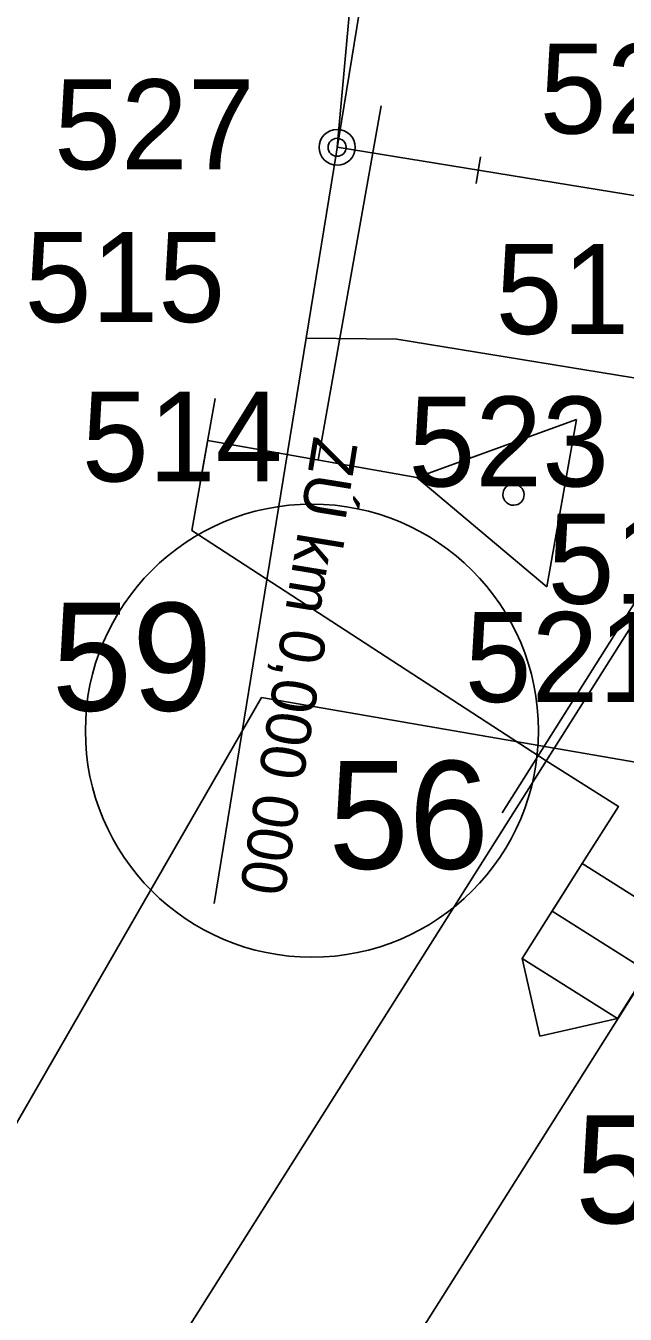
# Model space of a CAD drawing. Extents: x -743546 to -74, y -1128126 to -103.
# Drawn here: x -743185.96 to -743179.3, y -1127109.43 to -1127095.1 of the extents above; entities that cross this region are included whole.
import ezdxf

# ---------------------------------------------------------------- set-up
doc = ezdxf.new("R2010")
doc.units = 0
for name, color, linetype in [('_SVAH - Přesunutá', 7, 'Continuous'), ('_Zabezpečovací zařízení', 7, 'Continuous'), ('_Zabezpečovací zařízení_trasa', 7, 'Continuous'), ('bublina_fialová_čára_tenká', 7, 'Continuous'), ('KOMUNIKACE_KRAJNICE', 7, 'Continuous'), ('křížek', 7, 'Continuous'), ('křížky', 7, 'Continuous'), ('OSA_KOMUNIKACE', 7, 'Continuous'), ('OSA_POP', 7, 'Continuous'), ('SMER_VYS_VYROVNANI', 7, 'Continuous'), ('Vrstva 53', 7, 'Continuous'), ('Vrstva 60', 7, 'Continuous'), ('ŽBP', 7, 'Continuous')]:
    doc.layers.add(name, color=color, linetype=linetype)

# ---------------------------------------------------------------- blocks, each defined once
blk = doc.blocks.new('AeccTickCircle')
blk.add_circle((0, 0), 0.5)
blk = doc.blocks.new('POINT_DISPLAY')
blk.add_line((0, 0), (0, 0))

msp = doc.modelspace()

# ---------------------------------------------------------------- linework, layer by layer
at = {"layer": '_SVAH - Přesunutá'}
msp.add_lwpolyline([(-743178.679, -1127100.707), (-743180.665, -1127103.853)], dxfattribs=at)
at = {"layer": '_Zabezpečovací zařízení'}
for p, q in [((-743182.709, -1127099.929), (-743182.011, -1127095.99)), ((-743183.857, -1127099.245), (-743184.022, -1127100.176)), ((-743181.613, -1127100.122), (-743179.836, -1127099.477)), ((-743179.836, -1127099.477), (-743180.166, -1127101.338)), ((-743181.613, -1127100.122), (-743183.939, -1127099.711)), ((-743180.166, -1127101.338), (-743181.613, -1127100.122)), ((-743179.773, -1127104.416), (-743180.44, -1127105.473)), ((-743178.716, -1127105.083), (-743179.773, -1127104.416)), ((-743179.05, -1127105.611), (-743180.107, -1127104.945)), ((-743179.383, -1127106.14), (-743178.716, -1127105.083)), ((-743180.44, -1127105.473), (-743179.383, -1127106.14)), ((-743180.44, -1127105.473), (-743180.245, -1127106.335)), ((-743180.245, -1127106.335), (-743179.383, -1127106.14))]:
    msp.add_line(p, q, dxfattribs=at)
msp.add_lwpolyline([(-743179.773, -1127104.416), (-743180.107, -1127104.945), (-743179.05, -1127105.611), (-743178.716, -1127105.083), (-743179.773, -1127104.416)], dxfattribs=at)
for start, end in [(79.9608, 259.9608), (259.9608, 79.9608)]:
    msp.add_arc((-743180.538, -1127100.313), 0.118, start, end, dxfattribs=at)
at = {"layer": '_Zabezpečovací zařízení_trasa'}
for points in [[(-743049.28, -1126895.951), (-743072.487, -1126932.751), (-743098.647, -1126974.146), (-743125.94, -1127017.384), (-743152.604, -1127059.608), (-743175.023, -1127095.116), (-743199.163, -1127133.346), (-743215.971, -1127159.941), (-743232.818, -1127186.515), (-743247.456, -1127209.811), (-743254.52, -1127221.639), (-743261.299, -1127233.691), (-743264.155, -1127239.195), (-743264.862, -1127241.108), (-743267.337, -1127245.816)], [(-743183.942, -1127099.727), (-743184.117, -1127100.711), (-743180.174, -1127103.274)], [(-743180.542, -1127103.041), (-743180.542, -1127103.041)], [(-743179.773, -1127104.416), (-743179.372, -1127103.78), (-743180.174, -1127103.274)]]:
    msp.add_lwpolyline(points, dxfattribs=at)
at = {"layer": 'bublina_fialová_čára_tenká'}
msp.add_line((-743177.808, -1127044.792), (-743182.5, -1127096.45), dxfattribs=at)
at = {"layer": 'KOMUNIKACE_KRAJNICE'}
for q in [(-743182.159, -1127094.376), (-743181.834, -1127098.584)]:
    msp.add_line((-743182.845, -1127098.574), q, dxfattribs=at)
msp.add_lwpolyline([(-743178.176, -1127099.18), (-743181.834, -1127098.584)], dxfattribs=at)
at = {"layer": 'OSA_KOMUNIKACE'}
msp.add_line((-743164.284, -1127099.415), (-743182.5, -1127096.45), dxfattribs=at)
at = {"layer": 'OSA_POP'}
for p, q in [((-743180.954, -1127096.853), (-743180.906, -1127096.557)), ((-743182.845, -1127098.574), (-743183.869, -1127104.859))]:
    msp.add_line(p, q, dxfattribs=at)
at = {"layer": 'SMER_VYS_VYROVNANI'}
msp.add_lwpolyline([(-743178.712, -1127105.086), (-743197.526, -1127134.888)], dxfattribs=at)
at = {"layer": 'Vrstva 53'}
for points in [[(-743280.26, -1127263.68), (-743264.54, -1127233.06), (-743246.95, -1127204.21), (-743235.54, -1127186.77), (-743205.03, -1127140.21), (-743183.34, -1127102.57)], [(-743183.34, -1127102.57), (-743171.62, -1127104.6), (-743183.01, -1127122.02), (-743195.51, -1127141.13), (-743203.92, -1127154.43), (-743215.95, -1127172.74), (-743210.36, -1127174.02), (-743237.28, -1127205.49), (-743245.75, -1127220.06), (-743259.48, -1127245.93)]]:
    msp.add_lwpolyline(points, dxfattribs=at)
at = {"layer": 'Vrstva 60'}
for p, q in [((-743182.5, -1127096.45), (-743182.5, -1127096.45)), ((-743182.846, -1127098.574), (-743182.846, -1127098.574)), ((-743181.834, -1127098.584), (-743181.834, -1127098.584)), ((-743183.942, -1127099.727), (-743183.942, -1127099.727)), ((-743184.117, -1127100.711), (-743184.117, -1127100.711)), ((-743180.174, -1127103.274), (-743180.174, -1127103.274)), ((-743179.372, -1127103.78), (-743179.372, -1127103.78)), ((-743179.774, -1127104.416), (-743179.774, -1127104.416))]:
    msp.add_line(p, q, dxfattribs=at)
at = {"layer": 'ŽBP'}
msp.add_circle((-743182.78, -1127102.938), 2.52, dxfattribs=at)

# ---------------------------------------------------------------- block references
at = {"layer": 'křížek', "xscale": 10, "yscale": 10, "rotation": 61.14491455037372}
for p in [(-743182.5, -1127096.45), (-743182.846, -1127098.574), (-743181.834, -1127098.584)]:
    msp.add_blockref('POINT_DISPLAY', p, dxfattribs=at)
at = {"layer": 'křížky', "xscale": 10, "yscale": 10, "rotation": 61.14491455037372}
for p in [(-743183.942, -1127099.727), (-743184.117, -1127100.711), (-743180.174, -1127103.274), (-743179.372, -1127103.78), (-743179.774, -1127104.416)]:
    msp.add_blockref('POINT_DISPLAY', p, dxfattribs=at)
at = {"layer": 'OSA_POP', "rotation": -9.247996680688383}
for xscale, yscale in [(0.4, 0.39999999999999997), (0.2, 0.19999999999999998)]:
    msp.add_blockref('AeccTickCircle', (-743182.5, -1127096.45), dxfattribs=dict(at, xscale=xscale, yscale=yscale))

# ---------------------------------------------------------------- texts
at = {"layer": 'OSA_POP'}
msp.add_text('ZÚ km 0,000 000', height=0.5, rotation=260.752, dxfattribs=at).set_placement((-743182.76, -1127099.653))
at = {"layer": 'Vrstva 60'}
for s, height, p in [('526', 1, (-743180.247, -1127096.297)), ('527', 1, (-743185.648, -1127096.694)), ('515', 1, (-743185.977, -1127098.393)), ('513', 1, (-743180.737, -1127098.526)), ('514', 1, (-743185.34, -1127100.166)), ('523', 1, (-743181.707, -1127100.222)), ('512', 1, (-743180.159, -1127101.526)), ('59', 1.2, (-743185.674, -1127102.716)), ('521', 1, (-743181.081, -1127102.619)), ('56', 1.2, (-743182.596, -1127104.474)), ('58', 1.2, (-743179.855, -1127108.415))]:
    msp.add_text(s, height=height, dxfattribs=at).set_placement(p)

doc.saveas('drawing.dxf')
